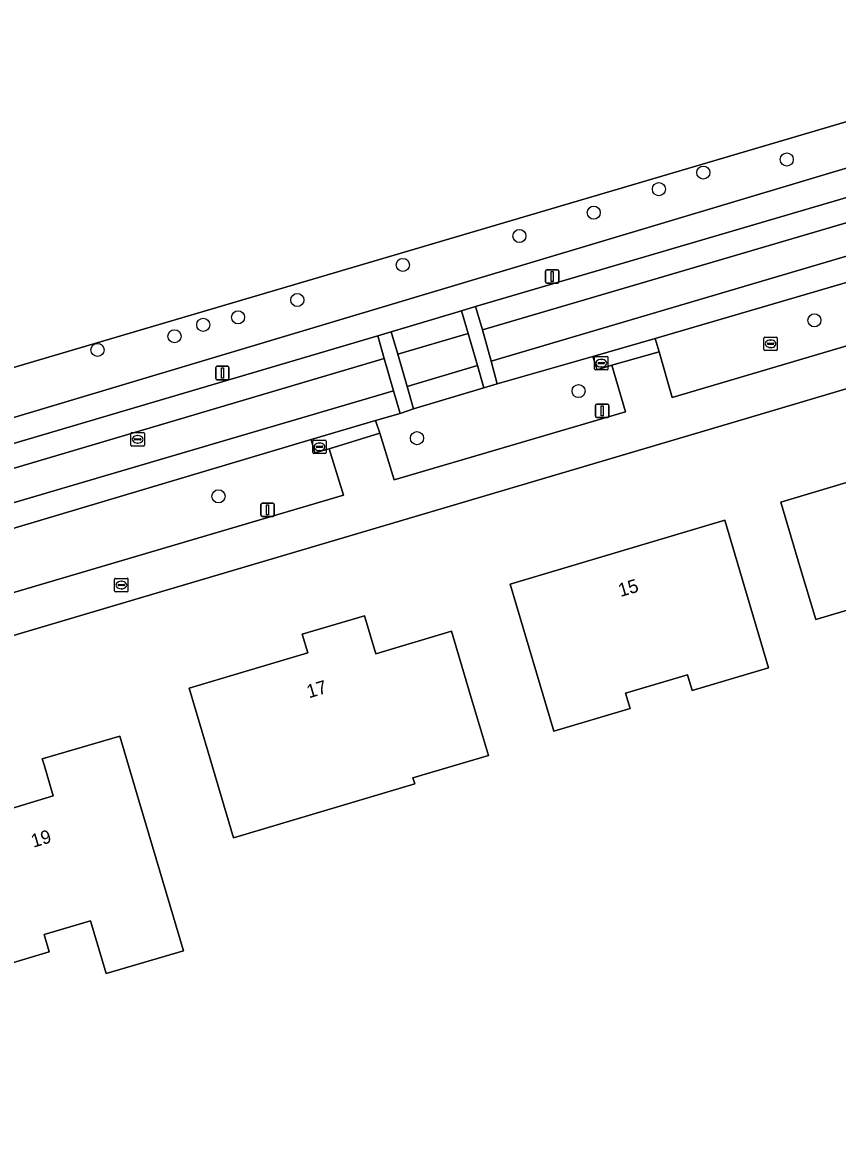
# Model space of a CAD drawing. Extents: x 162417 to 163722, y 384268 to 385417.
# Drawn here: x 163351.6 to 163412.4, y 384656 to 384740.3 of the extents above; entities that cross this region are included whole.
import ezdxf

# ---------------------------------------------------------------- set-up
doc = ezdxf.new("R2010")
doc.units = 0
for name, color, linetype in [('IMGEO_Boom', 7, 'Continuous'), ('IMGEO_Brandkraan', 7, 'Continuous'), ('IMGEO_Erf', 7, 'Continuous'), ('IMGEO_Groenvoorziening', 7, 'Continuous'), ('IMGEO_Kolk', 7, 'Continuous'), ('IMGEO_Lichtmast', 7, 'Continuous'), ('IMGEO_Pand', 7, 'Continuous'), ('IMGEO_Pand_nummerreeks', 7, 'Continuous'), ('IMGEO_Rijbaan_lokaal_gesloten', 7, 'Continuous'), ('IMGEO_Rijbaan_lokaal_open', 7, 'Continuous'), ('IMGEO_Rioolput', 7, 'Continuous'), ('IMGEO_Voetpad_open', 7, 'Continuous')]:
    doc.layers.add(name, color=color, linetype=linetype)

msp = doc.modelspace()

# ---------------------------------------------------------------- linework, layer by layer
at = {"layer": 'IMGEO_Boom'}
for centre in [(163408.633, 384730.094), (163402.403, 384729.114), (163399.087, 384727.877), (163394.222, 384726.126), (163388.672, 384724.381), (163379.968, 384722.221), (163372.089, 384719.604), (163367.667, 384718.312), (163365.066, 384717.749), (163410.699, 384718.087), (163362.92, 384716.899), (163357.17, 384715.879), (163393.089, 384712.807), (163381.023, 384709.286), (163366.204, 384704.947)]:
    msp.add_circle(centre, 0.489, dxfattribs=at)
at = {"layer": 'IMGEO_Brandkraan'}
for p, q in [((163358.444, 384697.895), (163358.444, 384698.747)), ((163358.519, 384698.821), (163359.371, 384698.821)), ((163358.932, 384698.601), (163358.957, 384698.601)), ((163359.445, 384698.747), (163359.445, 384697.895)), ((163359.371, 384697.821), (163358.519, 384697.821)), ((163358.703, 384698.315), (163358.703, 384698.327)), ((163359.141, 384698.278), (163358.743, 384698.278)), ((163358.746, 384698.364), (163359.144, 384698.364)), ((163358.955, 384698.041), (163358.93, 384698.041)), ((163359.187, 384698.327), (163359.187, 384698.315))]:
    msp.add_line(p, q, dxfattribs=at)
for points in [[(163358.444, 384697.895), (163358.444, 384698.747)], [(163358.519, 384698.821), (163359.371, 384698.821)], [(163359.445, 384698.747), (163359.445, 384697.895)], [(163359.371, 384697.821), (163358.519, 384697.821)]]:
    msp.add_lwpolyline(points, dxfattribs=at)
for centre, radius, start, end in [((163358.521, 384698.745), 0.0765, 91.55205, 178.44795), ((163358.521, 384698.745), 0.0765, 91.55205, 178.44795), ((163359.369, 384698.745), 0.0765, 1.55205, 88.44795), ((163359.369, 384698.745), 0.0765, 1.55205, 88.44795), ((163358.521, 384697.897), 0.0765, 181.55205, 268.44795), ((163358.521, 384697.897), 0.0765, 181.55205, 268.44795), ((163358.743, 384698.324), 0.0403, 85.87752, 175.75265), ((163358.74, 384698.314), 0.0366, 178.93798, 274.71019), ((163359.144, 384698.321), 0.043, 264.86636, 352.45326), ((163359.148, 384698.326), 0.0386, 1.73085, 96.63898), ((163359.369, 384697.897), 0.0765, 271.55205, 358.44795), ((163359.369, 384697.897), 0.0765, 271.55205, 358.44795)]:
    msp.add_arc(centre, radius, start, end, dxfattribs=at)
for centre, major_axis, ratio, start_param, end_param in [((163358.931, 384698.321), (-0.387, 0.002), 0.722429, 4.712389, 7.853982), ((163358.956, 384698.321), (-0.39, 0.002), 0.717154, 1.570796, 4.712389)]:
    msp.add_ellipse(centre, major_axis=major_axis, ratio=ratio, start_param=start_param, end_param=end_param, dxfattribs=at)
at = {"layer": 'IMGEO_Erf'}
for points in [[(163311.14, 384702.845), (163432.284, 384738.586), (163432.394, 384738.238), (163434.107, 384738.766)], [(163439.207, 384659.583), (163443.713, 384668.387), (163445.245, 384671.173), (163447.549, 384675.363), (163448.047, 384676.269), (163448.203, 384676.553), (163447.906, 384676.713), (163460.651, 384701.67), (163461.429, 384701.275), (163462.377, 384703.14), (163461.604, 384703.558), (163465.046, 384710.362), (163457.241, 384724.223), (163456.356, 384725.796), (163426.302, 384716.894), (163404.174, 384710.339), (163359.949, 384697.239), (163309.903, 384682.414), (163310.09, 384681.76), (163333.508, 384602.071)]]:
    msp.add_lwpolyline(points, dxfattribs=at)
for points in [[(163410.8, 384695.745), (163409.619, 384699.718), (163408.195, 384704.51), (163413.094, 384705.966), (163413.359, 384705.078), (163417.138, 384706.201), (163424.253, 384708.316), (163424.808, 384706.447), (163426.583, 384700.474), (163428.834, 384701.143), (163429.462, 384699.03), (163424.627, 384697.594), (163424.01, 384699.671)], [(163391.25, 384687.414), (163389.41, 384693.607), (163387.986, 384698.399), (163404, 384703.158), (163405.424, 384698.366), (163407.275, 384692.139), (163401.573, 384690.444), (163401.221, 384691.628), (163396.597, 384690.254), (163396.938, 384689.104)], [(163367.331, 384679.449), (163365.434, 384685.832), (163364.01, 384690.624), (163368.021, 384691.816), (163372.868, 384693.257), (163372.455, 384694.648), (163377.107, 384696.031), (163377.951, 384693.191), (163383.601, 384694.87), (163385.025, 384690.078), (163386.357, 384685.594), (163380.724, 384683.92), (163380.859, 384683.469)], [(163363.589, 384671.02), (163357.808, 384669.308), (163356.639, 384673.259), (163353.178, 384672.234), (163353.565, 384670.93), (163346.815, 384668.931), (163343.025, 384681.732), (163341.605, 384686.526), (163348.348, 384688.485), (163349.733, 384683.848), (163350.422, 384681.542), (163353.862, 384682.572), (163353.177, 384684.891), (163353.045, 384685.336), (163358.845, 384687.038), (163360.265, 384682.244)]]:
    msp.add_lwpolyline(points, close=True, dxfattribs=at)
at = {"layer": 'IMGEO_Groenvoorziening'}
for points in [[(163434.845, 384735.97), (163434.107, 384738.766), (163432.394, 384738.238), (163432.284, 384738.586), (163311.14, 384702.845), (163309.002, 384702.202), (163258.646, 384687.067), (163256.147, 384686.557), (163256.857, 384683.119), (163311.275, 384698.988), (163310.335, 384702.113), (163313.232, 384702.984), (163314.169, 384699.824)], [(163378.093, 384716.936), (163379.085, 384717.235), (163384.338, 384718.783), (163385.387, 384719.108), (163412.606, 384727.101), (163435.394, 384733.889), (163434.845, 384735.97), (163314.169, 384699.824), (163314.653, 384698.19)], [(163417.997, 384717.632), (163416.949, 384721.012), (163415.899, 384720.68), (163415.636, 384721.664), (163398.798, 384716.736), (163399.101, 384715.737), (163400.073, 384712.324)], [(163396.604, 384711.262), (163395.579, 384714.741), (163394.466, 384714.399), (163394.152, 384715.384), (163387.022, 384713.345), (163386.026, 384713.048), (163380.758, 384711.476), (163379.769, 384711.14), (163377.923, 384710.618), (163378.24, 384709.665), (163379.324, 384706.165)], [(163375.527, 384705.045), (163374.472, 384708.486), (163373.407, 384708.185), (163373.123, 384709.18), (163343.412, 384700.333), (163343.683, 384699.355), (163344.653, 384695.917)]]:
    msp.add_lwpolyline(points, close=True, dxfattribs=at)
at = {"layer": 'IMGEO_Kolk'}
for p, q in [((163394.284, 384714.461), (163394.284, 384715.313)), ((163394.359, 384715.387), (163395.211, 384715.387)), ((163395.285, 384715.313), (163395.285, 384714.461)), ((163394.543, 384714.881), (163394.543, 384714.893)), ((163394.981, 384714.844), (163394.583, 384714.844)), ((163394.586, 384714.93), (163394.984, 384714.93)), ((163394.795, 384714.607), (163394.77, 384714.607)), ((163394.772, 384715.167), (163394.797, 384715.167)), ((163395.027, 384714.893), (163395.027, 384714.881)), ((163395.211, 384714.387), (163394.359, 384714.387)), ((163373.245, 384708.218), (163373.245, 384709.07)), ((163373.32, 384709.144), (163374.172, 384709.144)), ((163373.504, 384708.638), (163373.504, 384708.65)), ((163373.942, 384708.601), (163373.544, 384708.601)), ((163373.547, 384708.687), (163373.945, 384708.687)), ((163373.733, 384708.924), (163373.758, 384708.924)), ((163373.988, 384708.65), (163373.988, 384708.638)), ((163374.246, 384709.07), (163374.246, 384708.218)), ((163374.172, 384708.144), (163373.32, 384708.144)), ((163373.756, 384708.364), (163373.731, 384708.364))]:
    msp.add_line(p, q, dxfattribs=at)
for points in [[(163394.284, 384714.461), (163394.284, 384715.313)], [(163394.359, 384715.387), (163395.211, 384715.387)], [(163395.285, 384715.313), (163395.285, 384714.461)], [(163395.211, 384714.387), (163394.359, 384714.387)], [(163373.245, 384708.218), (163373.245, 384709.07)], [(163373.32, 384709.144), (163374.172, 384709.144)], [(163374.246, 384709.07), (163374.246, 384708.218)], [(163374.172, 384708.144), (163373.32, 384708.144)]]:
    msp.add_lwpolyline(points, dxfattribs=at)
for centre, radius, start, end in [((163394.361, 384715.311), 0.0765, 91.55205, 178.44795), ((163394.361, 384715.311), 0.0765, 91.55205, 178.44795), ((163395.209, 384715.311), 0.0765, 1.55205, 88.44795), ((163395.209, 384715.311), 0.0765, 1.55205, 88.44795), ((163394.361, 384714.463), 0.0765, 181.55205, 268.44795), ((163394.361, 384714.463), 0.0765, 181.55205, 268.44795), ((163394.583, 384714.89), 0.0403, 85.87752, 175.75265), ((163394.58, 384714.88), 0.0366, 178.93798, 274.71019), ((163394.984, 384714.887), 0.043, 264.86636, 352.45326), ((163394.988, 384714.892), 0.0386, 1.73085, 96.63898), ((163395.209, 384714.463), 0.0765, 271.55205, 358.44795), ((163395.209, 384714.463), 0.0765, 271.55205, 358.44795), ((163373.322, 384709.068), 0.0765, 91.55205, 178.44795), ((163373.322, 384709.068), 0.0765, 91.55205, 178.44795), ((163373.544, 384708.647), 0.0403, 85.87752, 175.75265), ((163373.541, 384708.637), 0.0366, 178.93798, 274.71019), ((163373.945, 384708.644), 0.043, 264.86636, 352.45326), ((163373.949, 384708.649), 0.0386, 1.73085, 96.63898), ((163374.17, 384709.068), 0.0765, 1.55205, 88.44795), ((163374.17, 384709.068), 0.0765, 1.55205, 88.44795), ((163373.322, 384708.22), 0.0765, 181.55205, 268.44795), ((163373.322, 384708.22), 0.0765, 181.55205, 268.44795), ((163374.17, 384708.22), 0.0765, 271.55205, 358.44795), ((163374.17, 384708.22), 0.0765, 271.55205, 358.44795)]:
    msp.add_arc(centre, radius, start, end, dxfattribs=at)
for centre, major_axis, ratio, start_param, end_param in [((163394.771, 384714.887), (-0.387, 0.002), 0.722429, 4.712389, 7.853982), ((163394.796, 384714.887), (-0.39, 0.002), 0.717154, 1.570796, 4.712389), ((163373.732, 384708.644), (-0.387, 0.002), 0.722429, 4.712389, 7.853982), ((163373.757, 384708.644), (-0.39, 0.002), 0.717154, 1.570796, 4.712389)]:
    msp.add_ellipse(centre, major_axis=major_axis, ratio=ratio, start_param=start_param, end_param=end_param, dxfattribs=at)
at = {"layer": 'IMGEO_Lichtmast'}
for p, q in [((163390.622, 384720.962), (163390.622, 384721.762)), ((163390.622, 384721.762), (163390.622, 384720.962)), ((163390.722, 384721.862), (163391.512, 384721.862)), ((163391.512, 384721.862), (163390.722, 384721.862)), ((163391.612, 384721.762), (163391.612, 384720.962)), ((163391.612, 384720.962), (163391.612, 384721.762)), ((163391.512, 384720.862), (163390.722, 384720.862)), ((163390.722, 384720.862), (163391.512, 384720.862)), ((163365.996, 384713.753), (163365.996, 384714.553)), ((163365.996, 384714.553), (163365.996, 384713.753)), ((163366.096, 384714.653), (163366.886, 384714.653)), ((163366.886, 384714.653), (163366.096, 384714.653)), ((163366.986, 384714.553), (163366.986, 384713.753)), ((163366.986, 384713.753), (163366.986, 384714.553)), ((163366.886, 384713.653), (163366.096, 384713.653)), ((163366.096, 384713.653), (163366.886, 384713.653)), ((163394.354, 384710.935), (163394.354, 384711.735)), ((163394.354, 384711.735), (163394.354, 384710.935)), ((163394.454, 384711.835), (163395.244, 384711.835)), ((163395.244, 384711.835), (163394.454, 384711.835)), ((163395.344, 384711.735), (163395.344, 384710.935)), ((163395.344, 384710.935), (163395.344, 384711.735)), ((163395.244, 384710.835), (163394.454, 384710.835)), ((163394.454, 384710.835), (163395.244, 384710.835)), ((163369.373, 384703.534), (163369.373, 384704.334)), ((163369.373, 384704.334), (163369.373, 384703.534)), ((163369.473, 384704.434), (163370.263, 384704.434)), ((163370.263, 384704.434), (163369.473, 384704.434)), ((163370.363, 384704.334), (163370.363, 384703.534)), ((163370.363, 384703.534), (163370.363, 384704.334)), ((163370.263, 384703.434), (163369.473, 384703.434)), ((163369.473, 384703.434), (163370.263, 384703.434))]:
    msp.add_line(p, q, dxfattribs=at)
for points in [[(163391.042, 384721.737), (163391.192, 384721.737), (163391.192, 384720.987), (163391.042, 384720.987), (163391.042, 384721.737)], [(163366.416, 384714.528), (163366.566, 384714.528), (163366.566, 384713.778), (163366.416, 384713.778), (163366.416, 384714.528)], [(163394.774, 384711.71), (163394.924, 384711.71), (163394.924, 384710.96), (163394.774, 384710.96), (163394.774, 384711.71)], [(163369.793, 384704.309), (163369.943, 384704.309), (163369.943, 384703.559), (163369.793, 384703.559), (163369.793, 384704.309)]]:
    msp.add_lwpolyline(points, dxfattribs=at)
for centre, start, end in [((163390.722, 384721.762), 90, 180), ((163390.722, 384721.762), 90, 180), ((163391.512, 384721.762), 0, 90), ((163391.512, 384721.762), 360, 90), ((163390.722, 384720.962), 180, 270), ((163390.722, 384720.962), 180, 270), ((163391.512, 384720.962), 270, 0), ((163391.512, 384720.962), 270, 0), ((163366.096, 384714.553), 90, 180), ((163366.096, 384714.553), 90, 180), ((163366.886, 384714.553), 0, 90), ((163366.886, 384714.553), 360, 90), ((163366.096, 384713.753), 180, 270), ((163366.096, 384713.753), 180, 270), ((163366.886, 384713.753), 270, 0), ((163366.886, 384713.753), 270, 0), ((163394.454, 384711.735), 90, 180), ((163394.454, 384711.735), 90, 180), ((163395.244, 384711.735), 0, 90), ((163395.244, 384711.735), 360, 90), ((163394.454, 384710.935), 180, 270), ((163394.454, 384710.935), 180, 270), ((163395.244, 384710.935), 270, 0), ((163395.244, 384710.935), 270, 0), ((163369.473, 384704.334), 90, 180), ((163369.473, 384704.334), 90, 180), ((163370.263, 384704.334), 0, 90), ((163370.263, 384704.334), 360, 90), ((163369.473, 384703.534), 180, 270), ((163369.473, 384703.534), 180, 270), ((163370.263, 384703.534), 270, 0), ((163370.263, 384703.534), 270, 0)]:
    msp.add_arc(centre, 0.1, start, end, dxfattribs=at)
at = {"layer": 'IMGEO_Pand'}
for points in [[(163410.8, 384695.745), (163424.01, 384699.671), (163424.627, 384697.594), (163429.462, 384699.03), (163428.834, 384701.143), (163426.583, 384700.474), (163424.808, 384706.447), (163424.253, 384708.316), (163417.138, 384706.201), (163413.359, 384705.078), (163413.094, 384705.966), (163408.195, 384704.51), (163409.619, 384699.718)], [(163391.25, 384687.414), (163396.938, 384689.104), (163396.597, 384690.254), (163401.221, 384691.628), (163401.573, 384690.444), (163407.275, 384692.139), (163405.424, 384698.366), (163404, 384703.158), (163387.986, 384698.399), (163389.41, 384693.607)], [(163367.331, 384679.449), (163380.859, 384683.469), (163380.724, 384683.92), (163386.357, 384685.594), (163385.025, 384690.078), (163383.601, 384694.87), (163377.951, 384693.191), (163377.107, 384696.031), (163372.455, 384694.648), (163372.868, 384693.257), (163368.021, 384691.816), (163364.01, 384690.624), (163365.434, 384685.832)], [(163346.815, 384668.931), (163353.565, 384670.93), (163353.178, 384672.234), (163356.639, 384673.259), (163357.808, 384669.308), (163363.589, 384671.02), (163360.265, 384682.244), (163358.845, 384687.038), (163353.045, 384685.336), (163353.177, 384684.891), (163353.862, 384682.572), (163350.422, 384681.542), (163349.733, 384683.848), (163348.348, 384688.485), (163341.605, 384686.526), (163343.025, 384681.732)]]:
    msp.add_lwpolyline(points, close=True, dxfattribs=at)
at = {"layer": 'IMGEO_Rijbaan_lokaal_gesloten'}
for points in [[(163457.676, 384738.597), (163457.187, 384740.316), (163439.504, 384735.059), (163435.394, 384733.889), (163412.606, 384727.101), (163385.387, 384719.108), (163385.908, 384717.388), (163414.098, 384725.655)], [(163415.636, 384721.664), (163419.57, 384722.781), (163426.223, 384724.817), (163430.828, 384726.146), (163456.487, 384733.695), (163458.102, 384734.261), (163458.87, 384734.532), (163458.328, 384736.238), (163386.554, 384715.025), (163387.022, 384713.345), (163394.152, 384715.384), (163398.798, 384716.736)], [(163384.338, 384718.783), (163379.085, 384717.235), (163379.587, 384715.554), (163384.841, 384717.108)], [(163314.653, 384698.19), (163311.775, 384697.325), (163307.647, 384696.083), (163308.184, 384694.376), (163378.569, 384715.229), (163378.093, 384716.936)], [(163380.758, 384711.476), (163386.026, 384713.048), (163385.54, 384714.719), (163380.296, 384713.148)], [(163379.769, 384711.14), (163379.278, 384712.828), (163335.473, 384699.928), (163308.845, 384692.001), (163309.345, 384690.294), (163335.047, 384697.894), (163343.412, 384700.333), (163373.123, 384709.18), (163377.923, 384710.618)]]:
    msp.add_lwpolyline(points, close=True, dxfattribs=at)
at = {"layer": 'IMGEO_Rijbaan_lokaal_open'}
for points in [[(163457.676, 384738.597), (163414.098, 384725.655), (163385.908, 384717.388), (163386.554, 384715.025), (163458.328, 384736.238)], [(163384.338, 384718.783), (163384.841, 384717.108), (163385.54, 384714.719), (163386.026, 384713.048), (163387.022, 384713.345), (163386.554, 384715.025), (163385.908, 384717.388), (163385.387, 384719.108)], [(163379.769, 384711.14), (163380.758, 384711.476), (163380.296, 384713.148), (163379.587, 384715.554), (163379.085, 384717.235), (163378.093, 384716.936), (163378.569, 384715.229), (163379.278, 384712.828)], [(163379.587, 384715.554), (163380.296, 384713.148), (163385.54, 384714.719), (163384.841, 384717.108)], [(163379.278, 384712.828), (163378.569, 384715.229), (163308.184, 384694.376), (163308.845, 384692.001), (163335.473, 384699.928)]]:
    msp.add_lwpolyline(points, close=True, dxfattribs=at)
at = {"layer": 'IMGEO_Rioolput'}
for p, q in [((163406.925, 384715.911), (163406.925, 384716.763)), ((163407, 384716.837), (163407.852, 384716.837)), ((163407.184, 384716.331), (163407.184, 384716.343)), ((163407.622, 384716.294), (163407.224, 384716.294)), ((163407.227, 384716.38), (163407.625, 384716.38)), ((163407.413, 384716.617), (163407.438, 384716.617)), ((163407.668, 384716.343), (163407.668, 384716.331)), ((163407.926, 384716.763), (163407.926, 384715.911)), ((163407.852, 384715.837), (163407, 384715.837)), ((163407.436, 384716.057), (163407.411, 384716.057)), ((163359.668, 384708.776), (163359.668, 384709.628)), ((163359.743, 384709.702), (163360.595, 384709.702)), ((163360.156, 384709.482), (163360.181, 384709.482)), ((163360.669, 384709.628), (163360.669, 384708.776)), ((163360.595, 384708.702), (163359.743, 384708.702)), ((163359.927, 384709.196), (163359.927, 384709.208)), ((163360.365, 384709.159), (163359.967, 384709.159)), ((163359.97, 384709.245), (163360.368, 384709.245)), ((163360.179, 384708.922), (163360.154, 384708.922)), ((163360.411, 384709.208), (163360.411, 384709.196))]:
    msp.add_line(p, q, dxfattribs=at)
for points in [[(163406.925, 384715.911), (163406.925, 384716.763)], [(163407, 384716.837), (163407.852, 384716.837)], [(163407.926, 384716.763), (163407.926, 384715.911)], [(163407.852, 384715.837), (163407, 384715.837)], [(163359.668, 384708.776), (163359.668, 384709.628)], [(163359.743, 384709.702), (163360.595, 384709.702)], [(163360.669, 384709.628), (163360.669, 384708.776)], [(163360.595, 384708.702), (163359.743, 384708.702)]]:
    msp.add_lwpolyline(points, dxfattribs=at)
for centre, radius, start, end in [((163407.002, 384716.761), 0.0765, 91.55205, 178.44795), ((163407.002, 384716.761), 0.0765, 91.55205, 178.44795), ((163407.224, 384716.34), 0.0403, 85.87752, 175.75265), ((163407.221, 384716.33), 0.0366, 178.93798, 274.71019), ((163407.625, 384716.337), 0.043, 264.86636, 352.45326), ((163407.629, 384716.342), 0.0386, 1.73085, 96.63898), ((163407.85, 384716.761), 0.0765, 1.55205, 88.44795), ((163407.85, 384716.761), 0.0765, 1.55205, 88.44795), ((163407.002, 384715.913), 0.0765, 181.55205, 268.44795), ((163407.002, 384715.913), 0.0765, 181.55205, 268.44795), ((163407.85, 384715.913), 0.0765, 271.55205, 358.44795), ((163407.85, 384715.913), 0.0765, 271.55205, 358.44795), ((163359.745, 384709.626), 0.0765, 91.55205, 178.44795), ((163359.745, 384709.626), 0.0765, 91.55205, 178.44795), ((163360.593, 384709.626), 0.0765, 1.55205, 88.44795), ((163360.593, 384709.626), 0.0765, 1.55205, 88.44795), ((163359.745, 384708.778), 0.0765, 181.55205, 268.44795), ((163359.745, 384708.778), 0.0765, 181.55205, 268.44795), ((163359.967, 384709.205), 0.0403, 85.87752, 175.75265), ((163359.964, 384709.195), 0.0366, 178.93798, 274.71019), ((163360.368, 384709.202), 0.043, 264.86636, 352.45326), ((163360.372, 384709.207), 0.0386, 1.73085, 96.63898), ((163360.593, 384708.778), 0.0765, 271.55205, 358.44795), ((163360.593, 384708.778), 0.0765, 271.55205, 358.44795)]:
    msp.add_arc(centre, radius, start, end, dxfattribs=at)
for centre, major_axis, ratio, start_param, end_param in [((163407.412, 384716.337), (-0.387, 0.002), 0.722429, 4.712389, 7.853982), ((163407.437, 384716.337), (-0.39, 0.002), 0.717154, 1.570796, 4.712389), ((163360.155, 384709.202), (-0.387, 0.002), 0.722429, 4.712389, 7.853982), ((163360.18, 384709.202), (-0.39, 0.002), 0.717154, 1.570796, 4.712389)]:
    msp.add_ellipse(centre, major_axis=major_axis, ratio=ratio, start_param=start_param, end_param=end_param, dxfattribs=at)
at = {"layer": 'IMGEO_Voetpad_open'}
for points in [[(163417.997, 384717.632), (163400.073, 384712.324), (163399.101, 384715.737), (163395.579, 384714.741), (163396.604, 384711.262), (163379.324, 384706.165), (163378.24, 384709.665), (163374.472, 384708.486), (163375.527, 384705.045), (163344.653, 384695.917)], [(163309.903, 384682.414), (163359.949, 384697.239), (163404.174, 384710.339), (163426.302, 384716.894)]]:
    msp.add_lwpolyline(points, dxfattribs=at)
for points in [[(163395.579, 384714.741), (163399.101, 384715.737), (163398.798, 384716.736), (163394.152, 384715.384), (163394.466, 384714.399)], [(163377.923, 384710.618), (163373.123, 384709.18), (163373.407, 384708.185), (163374.472, 384708.486), (163378.24, 384709.665)]]:
    msp.add_lwpolyline(points, close=True, dxfattribs=at)

# ---------------------------------------------------------------- texts
at = {"layer": 'IMGEO_Pand_nummerreeks'}
for s, rotation, p in [('15', 16.55076, (163396.222, 384697.425)), ('17', 16.55434, (163372.959, 384689.862)), ('19', 16.66868, (163352.378, 384678.704))]:
    msp.add_text(s, height=1, rotation=rotation, dxfattribs=at).set_placement(p)

doc.saveas('drawing.dxf')
